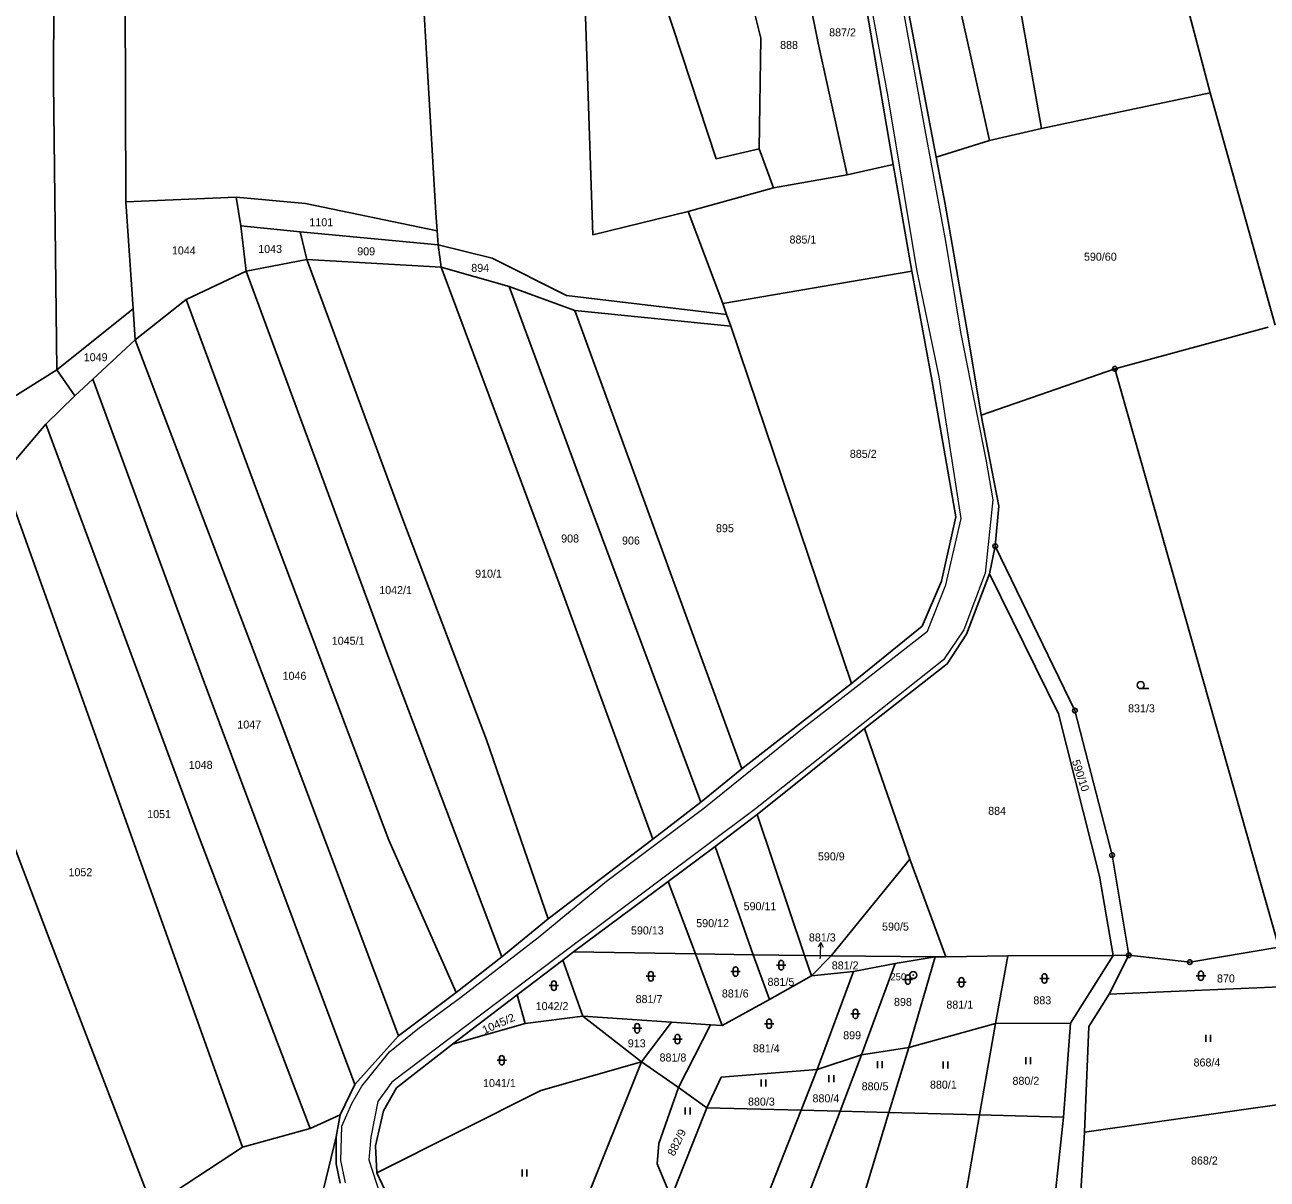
# Model space of a CAD drawing. Extents: x -820420 to -815896, y -1105820 to -1103643.
# Drawn here: x -817946 to -817682.2, y -1104558.3 to -1104313.2 of the extents above; entities that cross this region are included whole.
import ezdxf
from ezdxf.enums import TextEntityAlignment as Align

# ---------------------------------------------------------------- set-up
doc = ezdxf.new("R2010")
doc.units = 0
doc.header["$LTSCALE"] = 0.68
for name, color, linetype, lineweight in [('1', 7, 'Continuous', 25), ('3', 7, 'Continuous', 25), ('4', 7, 'Continuous', 13), ('7', 7, 'Continuous', 13), ('8', 7, 'Continuous', 25)]:
    doc.layers.add(name, color=color, linetype=linetype, lineweight=lineweight)
doc.layers.add('2', color=7, linetype='Continuous')

msp = doc.modelspace()

# ---------------------------------------------------------------- linework, layer by layer
at = {"layer": '1'}
for p, q in [((-817939.93, -1104325.42), (-817939.77, -1104242.98)), ((-817711.64, -1104261.34), (-817694.3, -1104327.63)), ((-817741.13, -1104337.73), (-817757.75, -1104263.43)), ((-817924.57, -1104350.77), (-817924.91, -1104270.05)), ((-817761.6, -1104342.8), (-817772.08, -1104281.65)), ((-817827.84, -1104285.92), (-817825.38, -1104357.77)), ((-817796.75, -1104287.76), (-817789.69, -1104315.96)), ((-817777.57, -1104317.08), (-817783.6, -1104286.05)), ((-817858.72, -1104353.09), (-817861.94, -1104299)), ((-817730.13, -1104335.16), (-817735.76, -1104303.07)), ((-817799.23, -1104341.62), (-817810.22, -1104308.09)), ((-817758.57, -1104309.27), (-817752.47, -1104341.27)), ((-817789.69, -1104315.96), (-817790.07, -1104339.47)), ((-817771.41, -1104345), (-817777.57, -1104317.08)), ((-817939.25, -1104386.44), (-817939.93, -1104325.42)), ((-817694.3, -1104327.63), (-817730.13, -1104335.16)), ((-817694.3, -1104327.63), (-817680.46, -1104376.93)), ((-817730.13, -1104335.16), (-817741.13, -1104337.73)), ((-817741.13, -1104337.73), (-817752.47, -1104341.27)), ((-817790.07, -1104339.47), (-817799.23, -1104341.62)), ((-817790.07, -1104339.47), (-817787.02, -1104347.79)), ((-817771.41, -1104345), (-817761.6, -1104342.8)), ((-817757.65, -1104365.47), (-817761.6, -1104342.8)), ((-817752.47, -1104341.27), (-817750.56, -1104351.28)), ((-817787.02, -1104347.79), (-817771.41, -1104345)), ((-817805.14, -1104352.79), (-817787.02, -1104347.79)), ((-817901.17, -1104349.74), (-817924.57, -1104350.77)), ((-817924.57, -1104350.77), (-817923.02, -1104373.51)), ((-817901.17, -1104349.74), (-817900.17, -1104355.82)), ((-817901.17, -1104349.74), (-817886.4, -1104351.1)), ((-817886.4, -1104351.1), (-817858.48, -1104356.89)), ((-817750.56, -1104351.28), (-817745.78, -1104378.98)), ((-817858.48, -1104356.89), (-817858.72, -1104353.09)), ((-817825.38, -1104357.77), (-817805.14, -1104352.79)), ((-817797.8, -1104372.31), (-817805.14, -1104352.79)), ((-817887.57, -1104357.11), (-817900.17, -1104355.82)), ((-817900.17, -1104355.82), (-817899.04, -1104365.45)), ((-817886.16, -1104363.01), (-817887.57, -1104357.11)), ((-817858.28, -1104359.87), (-817887.57, -1104357.11)), ((-817858.28, -1104359.87), (-817858.48, -1104356.89)), ((-817857.59, -1104364.6), (-817858.28, -1104359.87)), ((-817846.8, -1104362.74), (-817858.28, -1104359.87)), ((-817899.04, -1104365.45), (-817886.16, -1104363.01)), ((-817865.74, -1104418.22), (-817886.16, -1104363.01)), ((-817886.16, -1104363.01), (-817857.59, -1104364.6)), ((-817831, -1104370.65), (-817846.8, -1104362.74)), ((-817911.8, -1104371.48), (-817899.04, -1104365.45)), ((-817899.04, -1104365.45), (-817868.51, -1104448.21)), ((-817857.59, -1104364.6), (-817832.11, -1104432.92)), ((-817843.17, -1104368.73), (-817857.59, -1104364.6)), ((-817797.8, -1104372.31), (-817757.65, -1104365.47)), ((-817753.31, -1104388.94), (-817757.65, -1104365.47)), ((-817843.17, -1104368.73), (-817829.21, -1104373.82)), ((-817827.73, -1104410.56), (-817843.17, -1104368.73)), ((-817911.8, -1104371.48), (-817922.61, -1104380.06)), ((-817897.07, -1104411.33), (-817911.8, -1104371.48)), ((-817796.98, -1104374.71), (-817831, -1104370.65)), ((-817796.98, -1104374.71), (-817797.8, -1104372.31)), ((-817923.02, -1104373.51), (-817939.25, -1104386.44)), ((-817922.61, -1104380.06), (-817923.02, -1104373.51)), ((-817829.21, -1104373.82), (-817796.12, -1104377.19)), ((-817829.21, -1104373.82), (-817793.77, -1104471.19)), ((-817796.12, -1104377.19), (-817796.98, -1104374.71)), ((-817770.47, -1104453.08), (-817796.12, -1104377.19)), ((-817681.96, -1104377.39), (-817714.52, -1104386.21)), ((-817931.6, -1104388.4), (-817922.61, -1104380.06)), ((-817922.61, -1104380.06), (-817892, -1104460.44)), ((-817745.78, -1104378.98), (-817742.9, -1104396.04)), ((-817952.92, -1104395.01), (-817939.25, -1104386.44)), ((-817939.25, -1104386.44), (-817935.44, -1104391.94)), ((-817742.9, -1104396.04), (-817714.52, -1104386.21)), ((-817714.52, -1104386.21), (-817679.7, -1104509.03)), ((-817935.44, -1104391.94), (-817931.6, -1104388.4)), ((-817908.57, -1104451.09), (-817931.6, -1104388.4)), ((-817935.44, -1104391.94), (-817941.55, -1104397.99)), ((-817739.15, -1104415.38), (-817742.9, -1104396.04)), ((-817941.55, -1104397.99), (-817950.81, -1104408.79)), ((-817941.55, -1104397.99), (-817909.49, -1104484.42)), ((-817933.03, -1104458.56), (-817950.81, -1104408.79)), ((-817868.74, -1104486.36), (-817897.07, -1104411.33)), ((-817802.44, -1104478.24), (-817827.73, -1104410.56)), ((-817739.92, -1104423.9), (-817739.15, -1104415.38)), ((-817847.96, -1104465), (-817865.74, -1104418.22)), ((-817739.92, -1104423.9), (-817741.15, -1104429.76)), ((-817723.03, -1104458.82), (-817739.92, -1104423.9)), ((-817741.15, -1104429.76), (-817746.03, -1104442.61)), ((-817726.52, -1104459.49), (-817741.15, -1104429.76)), ((-817969.72, -1104431.39), (-817940.64, -1104507.75)), ((-817832.11, -1104432.92), (-817812.68, -1104486.11)), ((-817755.45, -1104440.86), (-817751.33, -1104431.3)), ((-817770.47, -1104453.08), (-817755.45, -1104440.86)), ((-817746.03, -1104442.61), (-817750.13, -1104448.88)), ((-817868.51, -1104448.21), (-817844.76, -1104511.08)), ((-817750.13, -1104448.88), (-817767.67, -1104462.62)), ((-817875.93, -1104538.23), (-817908.57, -1104451.09)), ((-817793.77, -1104471.19), (-817770.47, -1104453.08)), ((-817899.8, -1104551.51), (-817933.03, -1104458.56)), ((-817717.79, -1104494.01), (-817726.52, -1104459.49)), ((-817715.12, -1104489.51), (-817723.03, -1104458.82)), ((-817892, -1104460.44), (-817866.69, -1104527.9)), ((-817767.67, -1104462.62), (-817790.47, -1104480.91)), ((-817758.09, -1104490.37), (-817767.67, -1104462.62)), ((-817834.89, -1104503.02), (-817847.96, -1104465)), ((-817802.44, -1104478.24), (-817793.77, -1104471.19)), ((-817812.68, -1104486.11), (-817802.44, -1104478.24)), ((-817790.47, -1104480.91), (-817799.42, -1104487.65)), ((-817780.44, -1104510.81), (-817790.47, -1104480.91)), ((-817909.49, -1104484.42), (-817885.41, -1104547.59)), ((-817854.44, -1104518.7), (-817868.74, -1104486.36)), ((-817834.89, -1104503.02), (-817812.68, -1104486.11)), ((-817799.42, -1104487.65), (-817809.41, -1104495.08)), ((-817758.09, -1104490.37), (-817774.8, -1104510.89)), ((-817750.43, -1104511.11), (-817758.09, -1104490.37)), ((-817711.55, -1104510.77), (-817715.12, -1104489.51)), ((-817809.41, -1104495.08), (-817829.51, -1104510.07)), ((-817803.6, -1104510.46), (-817809.41, -1104495.08)), ((-817714.89, -1104510.83), (-817717.79, -1104494.01)), ((-817844.76, -1104511.08), (-817834.89, -1104503.02)), ((-817940.64, -1104507.75), (-817918.98, -1104564.11)), ((-817679.7, -1104509.03), (-817698.62, -1104512.22)), ((-817854.44, -1104518.7), (-817844.76, -1104511.08)), ((-817831.79, -1104511.82), (-817841.45, -1104519.2)), ((-817829.51, -1104510.07), (-817831.79, -1104511.82)), ((-817827.52, -1104523.72), (-817831.79, -1104511.82)), ((-817803.6, -1104510.46), (-817829.51, -1104510.07)), ((-817797.94, -1104525.72), (-817803.6, -1104510.46)), ((-817791.32, -1104510.65), (-817803.6, -1104510.46)), ((-817780.44, -1104510.81), (-817791.32, -1104510.65)), ((-817778.98, -1104515.15), (-817780.44, -1104510.81)), ((-817774.8, -1104510.89), (-817780.44, -1104510.81)), ((-817774.8, -1104510.89), (-817778.98, -1104515.15)), ((-817752.68, -1104511.14), (-817774.8, -1104510.89)), ((-817761.17, -1104512.55), (-817752.68, -1104511.14)), ((-817750.43, -1104511.11), (-817752.68, -1104511.14)), ((-817737.27, -1104510.91), (-817750.43, -1104511.11)), ((-817737.27, -1104510.91), (-817739.89, -1104525.3)), ((-817714.89, -1104510.83), (-817737.27, -1104510.91)), ((-817723.98, -1104525.18), (-817714.89, -1104510.83)), ((-817711.55, -1104510.77), (-817715.71, -1104519.03)), ((-817711.55, -1104510.77), (-817714.89, -1104510.83)), ((-817698.62, -1104512.22), (-817711.55, -1104510.77)), ((-817778.98, -1104515.15), (-817770.03, -1104514.21)), ((-817770.03, -1104514.21), (-817777.72, -1104535.02)), ((-817770.03, -1104514.21), (-817761.17, -1104512.55)), ((-817761.17, -1104512.55), (-817768.35, -1104531.92)), ((-817778.98, -1104515.15), (-817787.88, -1104520.16)), ((-817715.71, -1104519.03), (-817670.69, -1104517.13)), ((-817866.69, -1104527.9), (-817854.44, -1104518.7)), ((-817787.88, -1104520.16), (-817797.94, -1104525.72)), ((-817715.71, -1104519.03), (-817720.03, -1104525.91)), ((-817839.74, -1104525.26), (-817855.19, -1104529.69)), ((-817827.52, -1104523.72), (-817839.74, -1104525.26)), ((-817827.52, -1104523.72), (-817815.09, -1104533.38)), ((-817808.71, -1104525.01), (-817827.52, -1104523.72)), ((-817815.09, -1104533.38), (-817808.71, -1104525.01)), ((-817800.39, -1104525.56), (-817808.71, -1104525.01)), ((-817739.89, -1104525.3), (-817758.28, -1104530.37)), ((-817743.28, -1104544.69), (-817739.89, -1104525.3)), ((-817723.98, -1104525.18), (-817739.89, -1104525.3)), ((-817723.98, -1104525.18), (-817725.45, -1104545.17)), ((-817875.93, -1104538.23), (-817866.69, -1104527.9)), ((-817800.39, -1104525.56), (-817807.24, -1104538.89)), ((-817797.94, -1104525.72), (-817800.39, -1104525.56)), ((-817720.03, -1104525.91), (-817720.99, -1104548.38)), ((-817855.19, -1104529.69), (-817867.11, -1104538.9)), ((-817758.28, -1104530.37), (-817768.35, -1104531.92)), ((-817815.09, -1104533.38), (-817838.19, -1104591.31)), ((-817815.09, -1104533.38), (-817836.41, -1104539.47)), ((-817807.24, -1104538.89), (-817815.09, -1104533.38)), ((-817768.35, -1104531.92), (-817777.72, -1104535.02)), ((-817768.35, -1104531.92), (-817772.88, -1104543.9)), ((-817798.13, -1104536.64), (-817777.72, -1104535.02)), ((-817777.72, -1104535.02), (-817781.14, -1104543.68)), ((-817879.08, -1104544.64), (-817875.93, -1104538.23)), ((-817801.22, -1104543.15), (-817798.13, -1104536.64)), ((-817836.41, -1104539.47), (-817871.26, -1104557.02)), ((-817867.11, -1104538.9), (-817869.88, -1104543.85)), ((-817807.24, -1104538.89), (-817811.35, -1104550.76)), ((-817801.22, -1104543.15), (-817807.24, -1104538.89)), ((-817670.82, -1104541.23), (-817720.99, -1104548.38)), ((-817869.88, -1104543.85), (-817871.56, -1104551.27)), ((-817808.78, -1104562.2), (-817801.22, -1104543.15)), ((-817781.14, -1104543.68), (-817801.22, -1104543.15)), ((-817781.14, -1104543.68), (-817789.99, -1104566.14)), ((-817772.88, -1104543.9), (-817787.31, -1104581.61)), ((-817772.88, -1104543.9), (-817781.14, -1104543.68)), ((-817762.5, -1104544.18), (-817772.88, -1104543.9)), ((-817885.41, -1104547.59), (-817879.08, -1104544.64)), ((-817879.9, -1104549.33), (-817879.08, -1104544.64)), ((-817774.98, -1104585.06), (-817762.5, -1104544.18)), ((-817743.28, -1104544.69), (-817762.5, -1104544.18)), ((-817743.28, -1104544.69), (-817751.48, -1104591.65)), ((-817725.45, -1104545.17), (-817743.28, -1104544.69)), ((-817728.03, -1104569.58), (-817725.45, -1104545.17)), ((-817899.8, -1104551.51), (-817885.41, -1104547.59)), ((-817720.99, -1104548.38), (-817722.03, -1104565.39)), ((-817918.98, -1104564.11), (-817899.8, -1104551.51)), ((-817871.56, -1104551.27), (-817871.26, -1104557.02)), ((-817811.35, -1104550.76), (-817811.74, -1104555.08)), ((-817879.04, -1104559.18), (-817879.9, -1104555.08)), ((-817871.26, -1104557.02), (-817868.49, -1104562.86)), ((-817811.74, -1104555.08), (-817808.78, -1104562.2))]:
    msp.add_line(p, q, dxfattribs=at)
for points in [[(-817751.33, -1104431.3), (-817748.33, -1104417.65), (-817753.31, -1104388.94)], [(-817787.88, -1104520.16), (-817791.32, -1104510.65), (-817799.42, -1104487.65)], [(-817752.68, -1104511.14), (-817758.28, -1104530.37), (-817762.5, -1104544.18)], [(-817839.74, -1104525.26), (-817841.45, -1104519.2), (-817855.19, -1104529.69)], [(-817879.9, -1104555.08), (-817879.9, -1104549.33), (-817882.54, -1104560.2)]]:
    msp.add_lwpolyline(points, dxfattribs=at)
at = {"layer": '3'}
for p, q in [((-817709.053, -1104454.15), (-817707.303, -1104454.15)), ((-817813.571, -1104514.751), (-817813.571, -1104515.752)), ((-817812.569, -1104515.752), (-817812.569, -1104514.751)), ((-817796.081, -1104514.241), (-817794.079, -1104514.241)), ((-817795.581, -1104513.741), (-817795.581, -1104514.742)), ((-817794.579, -1104514.742), (-817794.579, -1104513.741)), ((-817786.381, -1104512.881), (-817784.379, -1104512.881)), ((-817785.881, -1104512.381), (-817785.881, -1104513.382)), ((-817784.879, -1104513.382), (-817784.879, -1104512.381)), ((-817696.741, -1104514.631), (-817696.741, -1104515.632)), ((-817695.739, -1104515.632), (-817695.739, -1104514.631)), ((-817834.661, -1104517.231), (-817832.659, -1104517.231)), ((-817834.161, -1104516.731), (-817834.161, -1104517.732)), ((-817833.159, -1104517.732), (-817833.159, -1104516.731)), ((-817814.071, -1104515.251), (-817812.069, -1104515.251)), ((-817759.491, -1104515.931), (-817757.489, -1104515.931)), ((-817758.991, -1104515.431), (-817758.991, -1104516.432)), ((-817757.989, -1104516.432), (-817757.989, -1104515.431)), ((-817748.121, -1104516.511), (-817746.119, -1104516.511)), ((-817747.621, -1104516.011), (-817747.621, -1104517.012)), ((-817746.619, -1104517.012), (-817746.619, -1104516.011)), ((-817730.481, -1104515.701), (-817728.479, -1104515.701)), ((-817729.981, -1104515.201), (-817729.981, -1104516.202)), ((-817728.979, -1104516.202), (-817728.979, -1104515.201)), ((-817697.241, -1104515.131), (-817695.239, -1104515.131)), ((-817770.131, -1104522.741), (-817770.131, -1104523.742)), ((-817769.129, -1104523.742), (-817769.129, -1104522.741)), ((-817788.971, -1104525.331), (-817786.969, -1104525.331)), ((-817788.471, -1104524.831), (-817788.471, -1104525.832)), ((-817787.469, -1104525.832), (-817787.469, -1104524.831)), ((-817770.631, -1104523.241), (-817768.629, -1104523.241)), ((-817816.971, -1104526.291), (-817814.969, -1104526.291)), ((-817816.471, -1104525.791), (-817816.471, -1104526.792)), ((-817815.469, -1104526.792), (-817815.469, -1104525.791)), ((-817807.931, -1104528.091), (-817807.931, -1104529.092)), ((-817806.929, -1104529.092), (-817806.929, -1104528.091)), ((-817695.221, -1104529.18), (-817695.221, -1104527.68)), ((-817694.22, -1104529.18), (-817694.22, -1104527.68)), ((-817808.431, -1104528.591), (-817806.429, -1104528.591)), ((-817845.751, -1104533.081), (-817843.749, -1104533.081)), ((-817845.251, -1104532.581), (-817845.251, -1104533.582)), ((-817844.249, -1104533.582), (-817844.249, -1104532.581)), ((-817764.921, -1104534.74), (-817764.921, -1104533.24)), ((-817763.92, -1104534.74), (-817763.92, -1104533.24)), ((-817751.001, -1104534.85), (-817751.001, -1104533.35)), ((-817750, -1104534.85), (-817750, -1104533.35)), ((-817733.471, -1104533.92), (-817733.471, -1104532.42)), ((-817732.47, -1104533.92), (-817732.47, -1104532.42)), ((-817789.641, -1104538.68), (-817789.641, -1104537.18)), ((-817788.64, -1104538.68), (-817788.64, -1104537.18)), ((-817775.251, -1104537.76), (-817775.251, -1104536.26)), ((-817774.25, -1104537.76), (-817774.25, -1104536.26)), ((-817805.761, -1104544.62), (-817805.761, -1104543.12)), ((-817804.76, -1104544.62), (-817804.76, -1104543.12)), ((-817840.441, -1104557.77), (-817840.441, -1104556.27)), ((-817839.44, -1104557.77), (-817839.44, -1104556.27))]:
    msp.add_line(p, q, dxfattribs=at)
msp.add_circle((-817709.0529, -1104453.3998), 0.75, dxfattribs=at)
for centre, start, end in [((-817785.38, -1104512.3809), 0, 180), ((-817813.07, -1104514.7509), 0, 180), ((-817795.08, -1104513.7409), 0, 180), ((-817795.08, -1104514.7409), 180, 359.98789), ((-817785.38, -1104513.3809), 180, 359.98789), ((-817758.49, -1104515.4309), 0, 180), ((-817729.48, -1104515.2009), 0, 180), ((-817696.24, -1104514.6309), 0, 180), ((-817833.66, -1104516.7309), 0, 180), ((-817813.07, -1104515.7509), 180, 359.98789), ((-817758.49, -1104516.4309), 180, 359.98789), ((-817747.12, -1104516.0109), 0, 180), ((-817747.12, -1104517.0109), 180, 359.98789), ((-817729.48, -1104516.2009), 180, 359.98789), ((-817696.24, -1104515.6309), 180, 359.98789), ((-817833.66, -1104517.7309), 180, 359.98789), ((-817769.63, -1104522.7409), 0, 180), ((-817815.97, -1104525.7909), 0, 180), ((-817787.97, -1104524.8309), 0, 180), ((-817769.63, -1104523.7409), 180, 359.98789), ((-817815.97, -1104526.7909), 180, 359.98789), ((-817807.43, -1104528.0909), 0, 180), ((-817787.97, -1104525.8309), 180, 359.98789), ((-817807.43, -1104529.0909), 180, 359.98789), ((-817844.75, -1104532.5809), 0, 180), ((-817844.75, -1104533.5809), 180, 359.98789)]:
    msp.add_arc(centre, 0.5, start, end, dxfattribs=at)
at = {"layer": '4'}
for p, q in [((-817762.7, -1104328.43), (-817771.22, -1104281.69)), ((-817760.96, -1104301.93), (-817754.87, -1104335.44)), ((-817756.61, -1104365.13), (-817762.7, -1104328.43)), ((-817754.87, -1104335.44), (-817750.47, -1104359.1)), ((-817750.47, -1104359.1), (-817747.34, -1104378.46)), ((-817751.85, -1104387.89), (-817756.61, -1104365.13)), ((-817747.34, -1104378.46), (-817743.73, -1104396.57)), ((-817747.2, -1104418), (-817751.85, -1104387.89)), ((-817743.73, -1104396.57), (-817741.88, -1104405.84)), ((-817741.88, -1104405.84), (-817740.45, -1104414.06)), ((-817740.45, -1104414.06), (-817742.09, -1104429.63)), ((-817750.46, -1104432.09), (-817747.2, -1104418)), ((-817754.32, -1104441.95), (-817750.46, -1104432.09)), ((-817770.11, -1104454.27), (-817754.32, -1104441.95)), ((-817750.93, -1104448.01), (-817790.85, -1104479.64)), ((-817780.17, -1104462.05), (-817770.11, -1104454.27)), ((-817801.85, -1104479.52), (-817780.17, -1104462.05)), ((-817790.85, -1104479.64), (-817832.79, -1104511.04)), ((-817822.49, -1104495.01), (-817801.85, -1104479.52)), ((-817837, -1104506.98), (-817822.49, -1104495.01)), ((-817832.79, -1104511.04), (-817868.1, -1104537.71)), ((-817868.6, -1104531.31), (-817862.55, -1104526.4)), ((-817874.49, -1104538.58), (-817868.6, -1104531.31)), ((-817876.57, -1104542.25), (-817874.49, -1104538.58)), ((-817868.1, -1104537.71), (-817871.07, -1104541.87)), ((-817878.7, -1104547.1), (-817876.57, -1104542.25)), ((-817871.07, -1104541.87), (-817872.55, -1104549.39)), ((-817878.95, -1104554.37), (-817878.7, -1104547.1)), ((-817872.55, -1104549.39), (-817872.95, -1104554.24)), ((-817877.91, -1104559.08), (-817878.95, -1104554.37)), ((-817872.95, -1104554.24), (-817870.57, -1104561.67))]:
    msp.add_line(p, q, dxfattribs=at)
for points in [[(-817742.09, -1104429.63), (-817746.62, -1104441.67), (-817750.93, -1104448.01)], [(-817862.55, -1104526.4), (-817853.54, -1104519.77), (-817837, -1104506.98)]]:
    msp.add_lwpolyline(points, dxfattribs=at)
at = {"layer": '7'}
msp.add_line((-817776.975, -1104508.051), (-817777.511, -1104509.034), dxfattribs=at)
msp.add_lwpolyline([(-817777.1, -1104511.53), (-817777.08, -1104511.05), (-817776.975, -1104508.051), (-817776.51, -1104509.069)], dxfattribs=at)
at = {"layer": '8'}
for centre, radius in [((-817714.52, -1104386.2099), 0.5), ((-817714.52, -1104386.2099), 0.0303), ((-817739.92, -1104423.8999), 0.5), ((-817739.92, -1104423.8999), 0.0303), ((-817723.03, -1104458.8199), 0.5), ((-817723.03, -1104458.8199), 0.0303), ((-817715.12, -1104489.5099), 0.5), ((-817715.12, -1104489.5099), 0.0303), ((-817711.55, -1104510.7699), 0.5), ((-817711.55, -1104510.7699), 0.0303), ((-817698.62, -1104512.2199), 0.5), ((-817698.62, -1104512.2199), 0.0303), ((-817757.35, -1104514.9898), 0.75), ((-817757.35, -1104514.9898), 0.03)]:
    msp.add_circle(centre, radius, dxfattribs=at)

# ---------------------------------------------------------------- texts
at = {"layer": '2'}
for s, p in [('887/2', (-817772.36, -1104315.605)), ('888', (-817783.729, -1104318.275)), ('1101', (-817883.07, -1104355.935)), ('885/1', (-817780.78, -1104359.605)), ('1044', (-817912.27, -1104361.935)), ('1043', (-817893.94, -1104361.605)), ('909', (-817873.539, -1104362.105)), ('590/60', (-817717.61, -1104363.255)), ('894', (-817849.319, -1104365.625)), ('1049', (-817930.99, -1104384.595)), ('885/2', (-817767.97, -1104405.125)), ('895', (-817797.349, -1104420.915)), ('908', (-817830.229, -1104423.105)), ('906', (-817817.299, -1104423.545)), ('910/1', (-817847.55, -1104430.565)), ('1042/1', (-817867.29, -1104434.075)), ('1045/1', (-817877.37, -1104444.825)), ('1046', (-817888.77, -1104452.275)), ('831/3', (-817708.88, -1104459.185)), ('1047', (-817898.37, -1104462.625)), ('1048', (-817908.68, -1104471.185)), ('1051', (-817917.52, -1104481.645)), ('884', (-817739.539, -1104480.955)), ('590/9', (-817774.75, -1104490.625)), ('1052', (-817934.23, -1104493.985)), ('590/11', (-817789.9, -1104501.215)), ('590/12', (-817799.96, -1104504.805)), ('590/5', (-817761.13, -1104505.535)), ('590/13', (-817813.82, -1104506.355)), ('881/2', (-817771.81, -1104513.775)), ('870', (-817690.939, -1104516.555)), ('881/5', (-817785.45, -1104517.275)), ('881/7', (-817813.47, -1104520.935)), ('881/6', (-817795.15, -1104519.745)), ('898', (-817759.539, -1104521.535)), ('883', (-817729.939, -1104521.185)), ('1042/2', (-817834.06, -1104522.425)), ('881/1', (-817747.47, -1104522.115)), ('899', (-817770.329, -1104528.615)), ('913', (-817816.079, -1104530.335)), ('881/4', (-817788.55, -1104531.405)), ('881/8', (-817808.38, -1104533.345)), ('868/4', (-817694.97, -1104534.395)), ('1041/1', (-817845.24, -1104538.765)), ('880/5', (-817765.46, -1104539.455)), ('880/1', (-817750.95, -1104539.105)), ('880/2', (-817733.43, -1104538.295)), ('880/3', (-817789.6, -1104542.705)), ('880/4', (-817775.9, -1104542.015)), ('868/2', (-817695.51, -1104555.225))]:
    msp.add_text(s, height=1.7, dxfattribs=at).set_placement(p, align=Align.CENTER)
msp.add_text('590/10', height=1.7, rotation=288, dxfattribs=at).set_placement((-817722.6004, -1104472.8543), align=Align.CENTER)
msp.add_text('881/3', height=1.7, dxfattribs=at).set_placement((-817779.51, -1104507.845))
at = {"layer": '2', "width": 1.05}
for s, rotation, p in [('1045/2', 24, (-817845.0902, -1104526.0697)), ('882/9', 64, (-817806.8154, -1104550.9066))]:
    msp.add_text(s, height=1.7, rotation=rotation, dxfattribs=at).set_placement(p, align=Align.CENTER)
at = {"layer": '8'}
msp.add_text('250', height=1.5, dxfattribs=at).set_placement((-817758.849, -1104516.107), align=Align.RIGHT)

doc.saveas('drawing.dxf')
